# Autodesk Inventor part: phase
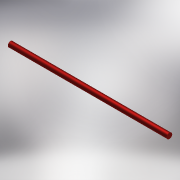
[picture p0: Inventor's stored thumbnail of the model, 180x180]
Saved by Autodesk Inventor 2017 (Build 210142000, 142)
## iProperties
Created: 2017-03
Part Number: phase
Material: Generic
Document SubType Name: Modeling
Designer: thierry.jost
Density: 1 g/cm^3
Appearance: Anodized - Red
Author: thierry.jost
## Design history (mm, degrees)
sketch "Sketch1"
  geometry: C1 r 2.5 at (0, 0); 1 further point
  constraints: 1 centre point, 1 coincident
  dimensions: "d0" = 5 diameter of C1
extrude "Extrusion1" new body sketch "Sketch1" distance "d1" = 150; taper "d2" = 0 deg
body "Solid1"
